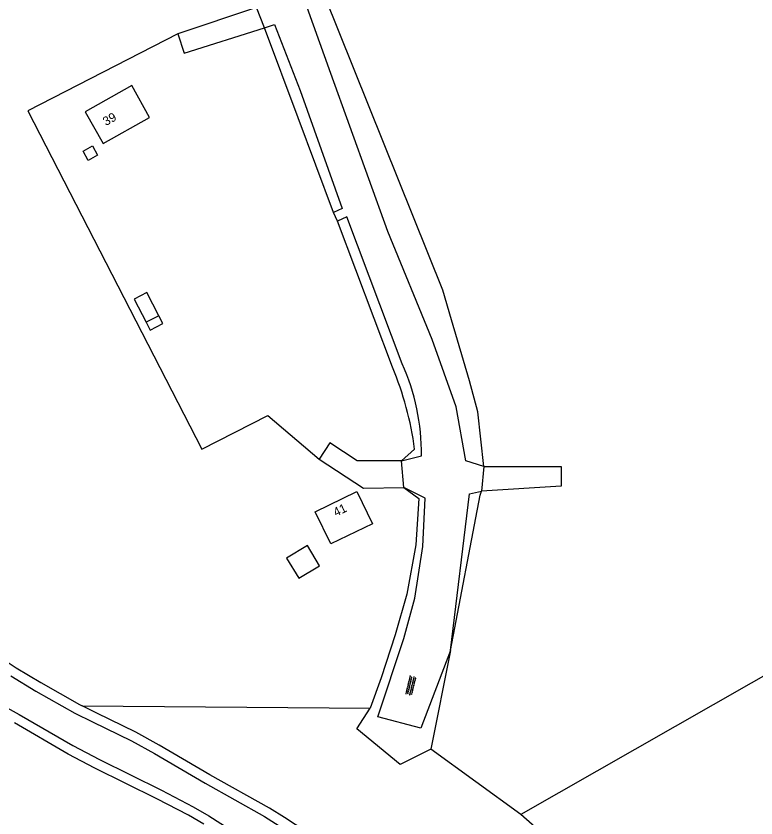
# Model space of a CAD drawing. Extents: x 126000 to 131009, y 393000 to 395500.
# Drawn here: x 129193.4 to 129276.7, y 395080.3 to 395170.7 of the extents above; entities that cross this region are included whole.
import ezdxf

# ---------------------------------------------------------------- set-up
doc = ezdxf.new("R2010")
doc.units = 0
for name, color, linetype in [('gg-afsc-draadraster', 7, 'Continuous'), ('gg-afsc-erfafscheiding', 7, 'Continuous'), ('gg-afsc-hekwerk', 7, 'Continuous'), ('gg-anno-huisnummerreeks BGT', 7, 'Continuous'), ('gg-bbg-bijgebouw', 7, 'Continuous'), ('gg-bbg-gedigitaliseerde bijgebouw', 7, 'Continuous'), ('gg-bbg-hoofdgebouw', 7, 'Continuous'), ('gg-bbg-luifel en loopbrug', 7, 'Continuous'), ('gg-knt-onverhard', 7, 'Continuous'), ('gg-kntw-bovenkant insteek waterloop', 7, 'Continuous'), ('gg-kntw-waterlijn', 7, 'Continuous'), ('gt-grn-vlakafsluiter', 7, 'Continuous'), ('gt-symb-overige verharding', 7, 'Continuous')]:
    doc.layers.add(name, color=color, linetype=linetype)

# ---------------------------------------------------------------- blocks, each defined once
blk = doc.blocks.new('gt0-OVH')
at = {"layer": 'gt-symb-overige verharding'}
for points in [[(-0.972, 0.298), (-0.967, 0.308), (-0.965, 0.319), (-0.966, 0.33), (-0.971, 0.34), (-0.978, 0.348), (-0.988, 0.353), (-0.999, 0.355), (-1.01, 0.354), (-1.02, 0.349), (-1.028, 0.342), (-1.033, 0.332), (-1.035, 0.321), (-1.034, 0.31), (-1.029, 0.3), (-1.022, 0.292), (-1.012, 0.287), (-1.001, 0.285), (-0.99, 0.286), (-0.98, 0.291)], [(-0.872, 0.106), (-0.867, 0.116), (-0.865, 0.126), (-0.866, 0.137), (-0.871, 0.147), (-0.878, 0.156), (-0.888, 0.161), (-0.899, 0.163), (-0.91, 0.162), (-0.92, 0.157), (-0.928, 0.15), (-0.933, 0.14), (-0.935, 0.129), (-0.934, 0.118), (-0.929, 0.108), (-0.922, 0.1), (-0.912, 0.095), (-0.901, 0.092), (-0.89, 0.094), (-0.88, 0.098)], [(-0.772, 0.298), (-0.767, 0.308), (-0.765, 0.319), (-0.766, 0.33), (-0.771, 0.34), (-0.778, 0.348), (-0.788, 0.353), (-0.799, 0.355), (-0.81, 0.354), (-0.82, 0.349), (-0.828, 0.342), (-0.833, 0.332), (-0.835, 0.321), (-0.834, 0.31), (-0.829, 0.3), (-0.822, 0.292), (-0.812, 0.287), (-0.801, 0.285), (-0.79, 0.286), (-0.78, 0.291)], [(-0.672, 0.106), (-0.667, 0.116), (-0.665, 0.126), (-0.666, 0.137), (-0.671, 0.147), (-0.678, 0.156), (-0.688, 0.161), (-0.699, 0.163), (-0.71, 0.162), (-0.72, 0.157), (-0.728, 0.15), (-0.733, 0.14), (-0.735, 0.129), (-0.734, 0.118), (-0.729, 0.108), (-0.722, 0.1), (-0.712, 0.095), (-0.701, 0.092), (-0.69, 0.094), (-0.68, 0.098)], [(-0.572, 0.298), (-0.567, 0.308), (-0.565, 0.319), (-0.566, 0.33), (-0.571, 0.34), (-0.578, 0.348), (-0.588, 0.353), (-0.599, 0.355), (-0.61, 0.354), (-0.62, 0.349), (-0.628, 0.342), (-0.633, 0.332), (-0.635, 0.321), (-0.634, 0.31), (-0.629, 0.3), (-0.622, 0.292), (-0.612, 0.287), (-0.601, 0.285), (-0.59, 0.286), (-0.58, 0.291)], [(-0.472, 0.106), (-0.467, 0.116), (-0.465, 0.126), (-0.466, 0.137), (-0.471, 0.147), (-0.478, 0.156), (-0.488, 0.161), (-0.499, 0.163), (-0.51, 0.162), (-0.52, 0.157), (-0.528, 0.15), (-0.533, 0.14), (-0.535, 0.129), (-0.534, 0.118), (-0.529, 0.108), (-0.522, 0.1), (-0.512, 0.095), (-0.501, 0.092), (-0.49, 0.094), (-0.48, 0.098)], [(-0.372, 0.298), (-0.367, 0.308), (-0.365, 0.319), (-0.366, 0.33), (-0.371, 0.34), (-0.378, 0.348), (-0.388, 0.353), (-0.399, 0.355), (-0.41, 0.354), (-0.42, 0.349), (-0.428, 0.342), (-0.433, 0.332), (-0.435, 0.321), (-0.434, 0.31), (-0.429, 0.3), (-0.422, 0.292), (-0.412, 0.287), (-0.401, 0.285), (-0.39, 0.286), (-0.38, 0.291)], [(-0.272, 0.106), (-0.267, 0.116), (-0.265, 0.126), (-0.266, 0.137), (-0.271, 0.147), (-0.278, 0.156), (-0.288, 0.161), (-0.299, 0.163), (-0.31, 0.162), (-0.32, 0.157), (-0.328, 0.15), (-0.333, 0.14), (-0.335, 0.129), (-0.334, 0.118), (-0.329, 0.108), (-0.322, 0.1), (-0.312, 0.095), (-0.301, 0.092), (-0.29, 0.094), (-0.28, 0.098)], [(-0.172, 0.298), (-0.167, 0.308), (-0.165, 0.319), (-0.166, 0.33), (-0.171, 0.34), (-0.178, 0.348), (-0.188, 0.353), (-0.199, 0.355), (-0.21, 0.354), (-0.22, 0.349), (-0.228, 0.342), (-0.233, 0.332), (-0.235, 0.321), (-0.234, 0.31), (-0.229, 0.3), (-0.222, 0.292), (-0.212, 0.287), (-0.201, 0.285), (-0.19, 0.286), (-0.18, 0.291)], [(-0.072, 0.106), (-0.067, 0.116), (-0.065, 0.126), (-0.066, 0.137), (-0.071, 0.147), (-0.078, 0.156), (-0.088, 0.161), (-0.099, 0.163), (-0.11, 0.162), (-0.12, 0.157), (-0.128, 0.15), (-0.133, 0.14), (-0.135, 0.129), (-0.134, 0.118), (-0.129, 0.108), (-0.122, 0.1), (-0.112, 0.095), (-0.101, 0.092), (-0.09, 0.094), (-0.08, 0.098)], [(0.028, 0.298), (0.033, 0.308), (0.035, 0.319), (0.034, 0.33), (0.029, 0.34), (0.022, 0.348), (0.012, 0.353), (0.001, 0.355), (-0.01, 0.354), (-0.02, 0.349), (-0.028, 0.342), (-0.033, 0.332), (-0.035, 0.321), (-0.034, 0.31), (-0.029, 0.3), (-0.022, 0.292), (-0.012, 0.287), (-0.001, 0.285), (0.01, 0.286), (0.02, 0.291)], [(0.128, 0.106), (0.133, 0.116), (0.135, 0.126), (0.134, 0.137), (0.129, 0.147), (0.122, 0.156), (0.112, 0.161), (0.101, 0.163), (0.09, 0.162), (0.08, 0.157), (0.072, 0.15), (0.067, 0.14), (0.065, 0.129), (0.066, 0.118), (0.071, 0.108), (0.078, 0.1), (0.088, 0.095), (0.099, 0.092), (0.11, 0.094), (0.12, 0.098)], [(0.228, 0.298), (0.233, 0.308), (0.235, 0.319), (0.234, 0.33), (0.229, 0.34), (0.222, 0.348), (0.212, 0.353), (0.201, 0.355), (0.19, 0.354), (0.18, 0.349), (0.172, 0.342), (0.167, 0.332), (0.165, 0.321), (0.166, 0.31), (0.171, 0.3), (0.178, 0.292), (0.188, 0.287), (0.199, 0.285), (0.21, 0.286), (0.22, 0.291)], [(0.328, 0.106), (0.333, 0.116), (0.335, 0.126), (0.334, 0.137), (0.329, 0.147), (0.322, 0.156), (0.312, 0.161), (0.301, 0.163), (0.29, 0.162), (0.28, 0.157), (0.272, 0.15), (0.267, 0.14), (0.265, 0.129), (0.266, 0.118), (0.271, 0.108), (0.278, 0.1), (0.288, 0.095), (0.299, 0.092), (0.31, 0.094), (0.32, 0.098)], [(0.428, 0.298), (0.433, 0.308), (0.435, 0.319), (0.434, 0.33), (0.429, 0.34), (0.422, 0.348), (0.412, 0.353), (0.401, 0.355), (0.39, 0.354), (0.38, 0.349), (0.372, 0.342), (0.367, 0.332), (0.365, 0.321), (0.366, 0.31), (0.371, 0.3), (0.378, 0.292), (0.388, 0.287), (0.399, 0.285), (0.41, 0.286), (0.42, 0.291)], [(0.528, 0.106), (0.533, 0.116), (0.535, 0.126), (0.534, 0.137), (0.529, 0.147), (0.522, 0.156), (0.512, 0.161), (0.501, 0.163), (0.49, 0.162), (0.48, 0.157), (0.472, 0.15), (0.467, 0.14), (0.465, 0.129), (0.466, 0.118), (0.471, 0.108), (0.478, 0.1), (0.488, 0.095), (0.499, 0.092), (0.51, 0.094), (0.52, 0.098)], [(0.628, 0.298), (0.633, 0.308), (0.635, 0.319), (0.634, 0.33), (0.629, 0.34), (0.622, 0.348), (0.612, 0.353), (0.601, 0.355), (0.59, 0.354), (0.58, 0.349), (0.572, 0.342), (0.567, 0.332), (0.565, 0.321), (0.566, 0.31), (0.571, 0.3), (0.578, 0.292), (0.588, 0.287), (0.599, 0.285), (0.61, 0.286), (0.62, 0.291)], [(0.728, 0.106), (0.733, 0.116), (0.735, 0.126), (0.734, 0.137), (0.729, 0.147), (0.722, 0.156), (0.712, 0.161), (0.701, 0.163), (0.69, 0.162), (0.68, 0.157), (0.672, 0.15), (0.667, 0.14), (0.665, 0.129), (0.666, 0.118), (0.671, 0.108), (0.678, 0.1), (0.688, 0.095), (0.699, 0.092), (0.71, 0.094), (0.72, 0.098)], [(0.828, 0.298), (0.833, 0.308), (0.835, 0.319), (0.834, 0.33), (0.829, 0.34), (0.822, 0.348), (0.812, 0.353), (0.801, 0.355), (0.79, 0.354), (0.78, 0.349), (0.772, 0.342), (0.767, 0.332), (0.765, 0.321), (0.766, 0.31), (0.771, 0.3), (0.778, 0.292), (0.788, 0.287), (0.799, 0.285), (0.81, 0.286), (0.82, 0.291)], [(0.928, 0.106), (0.933, 0.116), (0.935, 0.126), (0.934, 0.137), (0.929, 0.147), (0.922, 0.156), (0.912, 0.161), (0.901, 0.163), (0.89, 0.162), (0.88, 0.157), (0.872, 0.15), (0.867, 0.14), (0.865, 0.129), (0.866, 0.118), (0.871, 0.108), (0.878, 0.1), (0.888, 0.095), (0.899, 0.092), (0.91, 0.094), (0.92, 0.098)], [(1.028, 0.298), (1.033, 0.308), (1.035, 0.319), (1.034, 0.33), (1.029, 0.34), (1.022, 0.348), (1.012, 0.353), (1.001, 0.355), (0.99, 0.354), (0.98, 0.349), (0.972, 0.342), (0.967, 0.332), (0.965, 0.321), (0.966, 0.31), (0.971, 0.3), (0.978, 0.292), (0.988, 0.287), (0.999, 0.285), (1.01, 0.286), (1.02, 0.291)], [(-0.972, -0.142), (-0.967, -0.132), (-0.965, -0.121), (-0.966, -0.11), (-0.971, -0.1), (-0.978, -0.092), (-0.988, -0.087), (-0.999, -0.085), (-1.01, -0.086), (-1.02, -0.091), (-1.028, -0.098), (-1.033, -0.108), (-1.035, -0.119), (-1.034, -0.13), (-1.029, -0.14), (-1.022, -0.148), (-1.012, -0.153), (-1.001, -0.155), (-0.99, -0.154), (-0.98, -0.149)], [(-0.872, -0.334), (-0.867, -0.324), (-0.865, -0.314), (-0.866, -0.303), (-0.871, -0.293), (-0.878, -0.284), (-0.888, -0.279), (-0.899, -0.277), (-0.91, -0.278), (-0.92, -0.283), (-0.928, -0.29), (-0.933, -0.3), (-0.935, -0.311), (-0.934, -0.322), (-0.929, -0.332), (-0.922, -0.34), (-0.912, -0.345), (-0.901, -0.348), (-0.89, -0.346), (-0.88, -0.342)], [(-0.772, -0.142), (-0.767, -0.132), (-0.765, -0.121), (-0.766, -0.11), (-0.771, -0.1), (-0.778, -0.092), (-0.788, -0.087), (-0.799, -0.085), (-0.81, -0.086), (-0.82, -0.091), (-0.828, -0.098), (-0.833, -0.108), (-0.835, -0.119), (-0.834, -0.13), (-0.829, -0.14), (-0.822, -0.148), (-0.812, -0.153), (-0.801, -0.155), (-0.79, -0.154), (-0.78, -0.149)], [(-0.672, -0.334), (-0.667, -0.324), (-0.665, -0.314), (-0.666, -0.303), (-0.671, -0.293), (-0.678, -0.284), (-0.688, -0.279), (-0.699, -0.277), (-0.71, -0.278), (-0.72, -0.283), (-0.728, -0.29), (-0.733, -0.3), (-0.735, -0.311), (-0.734, -0.322), (-0.729, -0.332), (-0.722, -0.34), (-0.712, -0.345), (-0.701, -0.348), (-0.69, -0.346), (-0.68, -0.342)], [(-0.572, -0.142), (-0.567, -0.132), (-0.565, -0.121), (-0.566, -0.11), (-0.571, -0.1), (-0.578, -0.092), (-0.588, -0.087), (-0.599, -0.085), (-0.61, -0.086), (-0.62, -0.091), (-0.628, -0.098), (-0.633, -0.108), (-0.635, -0.119), (-0.634, -0.13), (-0.629, -0.14), (-0.622, -0.148), (-0.612, -0.153), (-0.601, -0.155), (-0.59, -0.154), (-0.58, -0.149)], [(-0.472, -0.334), (-0.467, -0.324), (-0.465, -0.314), (-0.466, -0.303), (-0.471, -0.293), (-0.478, -0.284), (-0.488, -0.279), (-0.499, -0.277), (-0.51, -0.278), (-0.52, -0.283), (-0.528, -0.29), (-0.533, -0.3), (-0.535, -0.311), (-0.534, -0.322), (-0.529, -0.332), (-0.522, -0.34), (-0.512, -0.345), (-0.501, -0.348), (-0.49, -0.346), (-0.48, -0.342)], [(-0.372, -0.142), (-0.367, -0.132), (-0.365, -0.121), (-0.366, -0.11), (-0.371, -0.1), (-0.378, -0.092), (-0.388, -0.087), (-0.399, -0.085), (-0.41, -0.086), (-0.42, -0.091), (-0.428, -0.098), (-0.433, -0.108), (-0.435, -0.119), (-0.434, -0.13), (-0.429, -0.14), (-0.422, -0.148), (-0.412, -0.153), (-0.401, -0.155), (-0.39, -0.154), (-0.38, -0.149)], [(-0.272, -0.334), (-0.267, -0.324), (-0.265, -0.314), (-0.266, -0.303), (-0.271, -0.293), (-0.278, -0.284), (-0.288, -0.279), (-0.299, -0.277), (-0.31, -0.278), (-0.32, -0.283), (-0.328, -0.29), (-0.333, -0.3), (-0.335, -0.311), (-0.334, -0.322), (-0.329, -0.332), (-0.322, -0.34), (-0.312, -0.345), (-0.301, -0.348), (-0.29, -0.346), (-0.28, -0.342)], [(-0.172, -0.142), (-0.167, -0.132), (-0.165, -0.121), (-0.166, -0.11), (-0.171, -0.1), (-0.178, -0.092), (-0.188, -0.087), (-0.199, -0.085), (-0.21, -0.086), (-0.22, -0.091), (-0.228, -0.098), (-0.233, -0.108), (-0.235, -0.119), (-0.234, -0.13), (-0.229, -0.14), (-0.222, -0.148), (-0.212, -0.153), (-0.201, -0.155), (-0.19, -0.154), (-0.18, -0.149)], [(-0.072, -0.334), (-0.067, -0.324), (-0.065, -0.314), (-0.066, -0.303), (-0.071, -0.293), (-0.078, -0.284), (-0.088, -0.279), (-0.099, -0.277), (-0.11, -0.278), (-0.12, -0.283), (-0.128, -0.29), (-0.133, -0.3), (-0.135, -0.311), (-0.134, -0.322), (-0.129, -0.332), (-0.122, -0.34), (-0.112, -0.345), (-0.101, -0.348), (-0.09, -0.346), (-0.08, -0.342)], [(0.028, -0.142), (0.033, -0.132), (0.035, -0.121), (0.034, -0.11), (0.029, -0.1), (0.022, -0.092), (0.012, -0.087), (0.001, -0.085), (-0.01, -0.086), (-0.02, -0.091), (-0.028, -0.098), (-0.033, -0.108), (-0.035, -0.119), (-0.034, -0.13), (-0.029, -0.14), (-0.022, -0.148), (-0.012, -0.153), (-0.001, -0.155), (0.01, -0.154), (0.02, -0.149)], [(0.128, -0.334), (0.133, -0.324), (0.135, -0.314), (0.134, -0.303), (0.129, -0.293), (0.122, -0.284), (0.112, -0.279), (0.101, -0.277), (0.09, -0.278), (0.08, -0.283), (0.072, -0.29), (0.067, -0.3), (0.065, -0.311), (0.066, -0.322), (0.071, -0.332), (0.078, -0.34), (0.088, -0.345), (0.099, -0.348), (0.11, -0.346), (0.12, -0.342)], [(0.228, -0.142), (0.233, -0.132), (0.235, -0.121), (0.234, -0.11), (0.229, -0.1), (0.222, -0.092), (0.212, -0.087), (0.201, -0.085), (0.19, -0.086), (0.18, -0.091), (0.172, -0.098), (0.167, -0.108), (0.165, -0.119), (0.166, -0.13), (0.171, -0.14), (0.178, -0.148), (0.188, -0.153), (0.199, -0.155), (0.21, -0.154), (0.22, -0.149)], [(0.328, -0.334), (0.333, -0.324), (0.335, -0.314), (0.334, -0.303), (0.329, -0.293), (0.322, -0.284), (0.312, -0.279), (0.301, -0.277), (0.29, -0.278), (0.28, -0.283), (0.272, -0.29), (0.267, -0.3), (0.265, -0.311), (0.266, -0.322), (0.271, -0.332), (0.278, -0.34), (0.288, -0.345), (0.299, -0.348), (0.31, -0.346), (0.32, -0.342)], [(0.428, -0.142), (0.433, -0.132), (0.435, -0.121), (0.434, -0.11), (0.429, -0.1), (0.422, -0.092), (0.412, -0.087), (0.401, -0.085), (0.39, -0.086), (0.38, -0.091), (0.372, -0.098), (0.367, -0.108), (0.365, -0.119), (0.366, -0.13), (0.371, -0.14), (0.378, -0.148), (0.388, -0.153), (0.399, -0.155), (0.41, -0.154), (0.42, -0.149)], [(0.528, -0.334), (0.533, -0.324), (0.535, -0.314), (0.534, -0.303), (0.529, -0.293), (0.522, -0.284), (0.512, -0.279), (0.501, -0.277), (0.49, -0.278), (0.48, -0.283), (0.472, -0.29), (0.467, -0.3), (0.465, -0.311), (0.466, -0.322), (0.471, -0.332), (0.478, -0.34), (0.488, -0.345), (0.499, -0.348), (0.51, -0.346), (0.52, -0.342)], [(0.628, -0.142), (0.633, -0.132), (0.635, -0.121), (0.634, -0.11), (0.629, -0.1), (0.622, -0.092), (0.612, -0.087), (0.601, -0.085), (0.59, -0.086), (0.58, -0.091), (0.572, -0.098), (0.567, -0.108), (0.565, -0.119), (0.566, -0.13), (0.571, -0.14), (0.578, -0.148), (0.588, -0.153), (0.599, -0.155), (0.61, -0.154), (0.62, -0.149)], [(0.728, -0.334), (0.733, -0.324), (0.735, -0.314), (0.734, -0.303), (0.729, -0.293), (0.722, -0.284), (0.712, -0.279), (0.701, -0.277), (0.69, -0.278), (0.68, -0.283), (0.672, -0.29), (0.667, -0.3), (0.665, -0.311), (0.666, -0.322), (0.671, -0.332), (0.678, -0.34), (0.688, -0.345), (0.699, -0.348), (0.71, -0.346), (0.72, -0.342)], [(0.828, -0.142), (0.833, -0.132), (0.835, -0.121), (0.834, -0.11), (0.829, -0.1), (0.822, -0.092), (0.812, -0.087), (0.801, -0.085), (0.79, -0.086), (0.78, -0.091), (0.772, -0.098), (0.767, -0.108), (0.765, -0.119), (0.766, -0.13), (0.771, -0.14), (0.778, -0.148), (0.788, -0.153), (0.799, -0.155), (0.81, -0.154), (0.82, -0.149)], [(0.928, -0.334), (0.933, -0.324), (0.935, -0.314), (0.934, -0.303), (0.929, -0.293), (0.922, -0.284), (0.912, -0.279), (0.901, -0.277), (0.89, -0.278), (0.88, -0.283), (0.872, -0.29), (0.867, -0.3), (0.865, -0.311), (0.866, -0.322), (0.871, -0.332), (0.878, -0.34), (0.888, -0.345), (0.899, -0.348), (0.91, -0.346), (0.92, -0.342)], [(1.028, -0.142), (1.033, -0.132), (1.035, -0.121), (1.034, -0.11), (1.029, -0.1), (1.022, -0.092), (1.012, -0.087), (1.001, -0.085), (0.99, -0.086), (0.98, -0.091), (0.972, -0.098), (0.967, -0.108), (0.965, -0.119), (0.966, -0.13), (0.971, -0.14), (0.978, -0.148), (0.988, -0.153), (0.999, -0.155), (1.01, -0.154), (1.02, -0.149)]]:
    blk.add_lwpolyline(points, close=True, dxfattribs=at)

msp = doc.modelspace()

# ---------------------------------------------------------------- linework, layer by layer
at = {"layer": 'gg-afsc-draadraster'}
for p, q in [((129225.133, 395159.177), (129221.353, 395169.325)), ((129229.111, 395148.495), (129225.133, 395159.177)), ((129235.756, 395131.089), (129229.582, 395147.523)), ((129236.798, 395120.54), (129238.26, 395121.836)), ((129242.311, 395099.143), (129240.076, 395088.019)), ((129200.789, 395092.934), (129233.236, 395092.649))]:
    msp.add_line(p, q, dxfattribs=at)
for points in [[(129246.045, 395119.899), (129245.365, 395126.054), (129244.454, 395129.554), (129242.402, 395136.398), (129241.446, 395139.752), (129224.747, 395181.32), (129225.635, 395182.899)], [(129237.026, 395117.505), (129238.718, 395116.267), (129238.393, 395111.066), (129237.397, 395105.5), (129236.068, 395100.905), (129234.483, 395096.059), (129233.236, 395092.649)], [(129242.311, 395099.143), (129245.635, 395116.665), (129245.779, 395117.106)], [(129240.076, 395088.019), (129236.633, 395086.317), (129231.759, 395090.315), (129233.236, 395092.649)]]:
    msp.add_lwpolyline(points, dxfattribs=at)
msp.add_arc((129202.313, 395117.073), 36.261, 7.54699, 22.73783, dxfattribs=at)
at = {"layer": 'gg-afsc-erfafscheiding'}
msp.add_lwpolyline([(129223.839, 395109.572), (129225.206, 395107.297), (129227.547, 395108.704), (129226.181, 395110.975), (129223.839, 395109.572)], dxfattribs=at)
at = {"layer": 'gg-afsc-hekwerk'}
for p, q in [((129221.353, 395169.325), (129220.46, 395171.601)), ((129229.582, 395147.523), (129229.111, 395148.495)), ((129237.026, 395117.505), (129236.798, 395120.54)), ((129246.045, 395119.899), (129245.779, 395117.106))]:
    msp.add_line(p, q, dxfattribs=at)
at = {"layer": 'gg-bbg-bijgebouw'}
msp.add_lwpolyline([(129200.905, 395155.419), (129201.951, 395156.006), (129202.539, 395154.96), (129201.493, 395154.372), (129200.905, 395155.419)], dxfattribs=at)
at = {"layer": 'gg-bbg-gedigitaliseerde bijgebouw'}
msp.add_line((129209.439, 395136.885), (129208.016, 395136.153), dxfattribs=at)
msp.add_lwpolyline([(129208.016, 395136.153), (129208.474, 395135.263), (129209.897, 395135.996), (129209.439, 395136.885)], dxfattribs=at)
at = {"layer": 'gg-bbg-hoofdgebouw'}
for points in [[(129201.161, 395159.864), (129203.169, 395156.289), (129208.405, 395159.23), (129206.397, 395162.805), (129201.161, 395159.864)], [(129227.057, 395114.794), (129231.752, 395117.078), (129233.528, 395113.444), (129228.833, 395111.16), (129227.057, 395114.794)]]:
    msp.add_lwpolyline(points, dxfattribs=at)
at = {"layer": 'gg-bbg-luifel en loopbrug'}
msp.add_lwpolyline([(129209.439, 395136.885), (129208.094, 395139.496), (129206.672, 395138.763), (129208.016, 395136.153)], dxfattribs=at)
at = {"layer": 'gg-knt-onverhard'}
for p, q in [((129220.46, 395171.601), (129211.564, 395168.646)), ((129236.798, 395120.54), (129239.048, 395121.106))]:
    msp.add_line(p, q, dxfattribs=at)
for points in [[(129246.045, 395119.899), (129244.025, 395120.542), (129242.949, 395126.601), (129240.247, 395134.204), (129235.255, 395146.359), (129228.812, 395164.162), (129222.944, 395180.539), (129225.493, 395183.036)], [(129211.564, 395168.646), (129212.291, 395166.459), (129221.353, 395169.325)], [(129221.353, 395169.325), (129222.466, 395169.702), (129225.371, 395162.254), (129230.089, 395148.976), (129229.111, 395148.495)], [(129236.87, 395131.466), (129230.638, 395148.032), (129229.582, 395147.523)], [(129236.798, 395120.54), (129231.795, 395120.54), (129228.707, 395122.566), (129227.501, 395120.727)], [(129227.501, 395120.727), (129232.489, 395117.454), (129237.026, 395117.505)], [(129246.045, 395119.899), (129254.749, 395119.899), (129254.749, 395117.668), (129245.779, 395117.106)], [(129242.311, 395099.143), (129238.948, 395090.407), (129234.132, 395091.692), (129237.043, 395100.487), (129238.288, 395105.055), (129239.197, 395110.873), (129239.427, 395116.324), (129237.026, 395117.505)], [(129242.311, 395099.143), (129244.444, 395116.801), (129245.779, 395117.106)]]:
    msp.add_lwpolyline(points, dxfattribs=at)
msp.add_arc((129213.325, 395121.107), 25.723, 359.99732, 23.74766, dxfattribs=at)
at = {"layer": 'gg-kntw-bovenkant insteek waterloop'}
for points in [[(129191.682, 395098.311), (129193.358, 395097.211), (129196.156, 395095.535), (129200.51, 395093.076), (129200.789, 395092.934)], [(129231.53, 395076.17), (129230.679, 395075.662), (129223.611, 395080.315), (129221.919, 395081.38), (129215.197, 395085.149), (129209.48, 395088.496), (129206.855, 395089.947), (129202.449, 395092.09), (129200.789, 395092.934)], [(129214.502, 395079.583), (129212.772, 395080.586), (129209.228, 395082.45), (129202.248, 395085.874), (129199.224, 395087.487), (129193.169, 395090.999)]]:
    msp.add_lwpolyline(points, dxfattribs=at)
at = {"layer": 'gg-kntw-waterlijn'}
for points in [[(129192.773, 395096.279), (129195.603, 395094.584), (129199.99, 395092.106), (129201.959, 395091.105), (129206.348, 395088.97), (129208.936, 395087.54), (129214.65, 395084.195), (129221.357, 395080.434), (129223.016, 395079.39)], [(129189.473, 395094.259), (129193.708, 395091.958), (129199.759, 395088.448), (129202.749, 395086.853), (129209.726, 395083.431), (129213.304, 395081.549), (129215.075, 395080.522), (129217.351, 395079.065)]]:
    msp.add_lwpolyline(points, dxfattribs=at)
at = {"layer": 'gt-grn-vlakafsluiter'}
for p, q in [((129250.206, 395080.67), (129240.076, 395088.019)), ((129275.536, 395058.556), (129250.206, 395080.67))]:
    msp.add_line(p, q, dxfattribs=at)
for points in [[(129211.564, 395168.646), (129194.676, 395159.956), (129214.295, 395121.828), (129221.714, 395125.645), (129227.501, 395120.727)], [(129366.09, 395094.638), (129340.911, 395132.383), (129250.206, 395080.67)]]:
    msp.add_lwpolyline(points, dxfattribs=at)

# ---------------------------------------------------------------- block references
at = {"layer": 'gt-symb-overige verharding', "rotation": 76.22785456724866}
msp.add_blockref('gt0-OVH', (129237.835, 395095.196), dxfattribs=at)

# ---------------------------------------------------------------- texts
at = {"layer": 'gg-anno-huisnummerreeks BGT'}
for s, rotation, p in [('39', 29.3, (129203.48, 395158.243)), ('41', 25.9, (129229.388, 395114.211))]:
    msp.add_text(s, height=1, rotation=rotation, dxfattribs=at).set_placement(p)

doc.saveas('drawing.dxf')
